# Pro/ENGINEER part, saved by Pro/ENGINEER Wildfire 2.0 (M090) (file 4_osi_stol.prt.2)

Other parameters: PALLET_SIZE_MM, NUM_MTP_HOLES, NUM_MOUNT_HOLES, WEIGHT_LB, THREAD_PER_INCH, d109, d13, d111, d10, d108, d155, d157, d154, d162, d163, d165, d174, d171, d172, d180, d177, d178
